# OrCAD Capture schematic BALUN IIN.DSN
size A
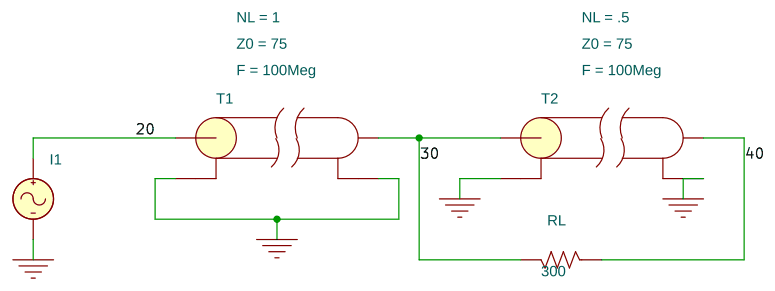
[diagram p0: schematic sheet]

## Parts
I1  IAC
RL  300  [AX/RC05]
T1  T
T2  T

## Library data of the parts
I1 = IAC: ACPHASE: 180
RL = R
T1 = T: F: 100Meg; NL: 1; Z0: 75
T2 = T: F: 100Meg; NL: .5; Z0: 75

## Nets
0: I1.2(-) T1.2(A-) T1.4(B-) T2.2(A-) T2.4(B-)
20: I1.1(+) T1.1(A+)
30: RL.2 T1.3(B+) T2.1(A+)
40: RL.1 T2.3(B+)
